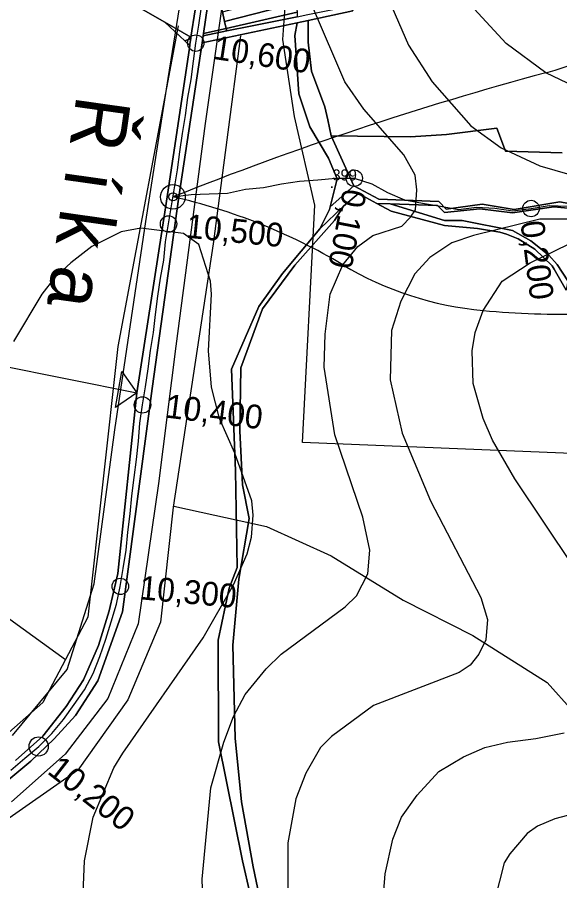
# Model space of a CAD drawing. Extents: x -510989 to -501240, y -1184665 to -1176089.
# Drawn here: x -509339.7 to -509042.8, y -1180518.8 to -1180046.7 of the extents above; entities that cross this region are included whole.
import ezdxf

# ---------------------------------------------------------------- set-up
doc = ezdxf.new("R2010")
doc.units = 0
for name, color, linetype in [('NAVRH_revitalizace_toku', 7, 'Continuous'), ('NAVRH_rozvodnice', 7, 'Continuous'), ('orna_puda', 7, 'Continuous'), ('ostatni_plocha_x_manipulacni_plocha', 7, 'Continuous'), ('ostatni_plocha_x_neplodna_puda', 7, 'Continuous'), ('ostatni_plocha_x_ostatni_komunikace', 7, 'Continuous'), ('STAV_odtokove_linie', 7, 'Continuous'), ('STAV_systematicke_odvodneni', 7, 'Continuous'), ('STAV_vyrazne_udolnice', 7, 'Continuous'), ('trasovani_toku', 7, 'Continuous'), ('trvaly_travni_porost', 7, 'Continuous'), ('vodni_plocha_x_vodni_tok_v_koryt_prir_n_upr', 7, 'Continuous'), ('vodni_plocha_x_vodni_tok_v_koryte_umelem', 7, 'Continuous'), ('vrstevnice_01', 7, 'Continuous'), ('vrstevnice_02', 7, 'Continuous'), ('vrstevnice_05', 7, 'Continuous')]:
    doc.layers.add(name, color=color, linetype=linetype)

msp = doc.modelspace()

# ---------------------------------------------------------------- linework, layer by layer
at = {"layer": 'NAVRH_revitalizace_toku'}
for points in [[(-509251.68, -1180051.44), (-509284.55, -1180226.79), (-509300.99, -1180374.75), (-509325.65, -1180421.33), (-509370.86, -1180461.06), (-509421.55, -1180503.53), (-509437.68, -1180558.22), (-509431.14, -1180593.95), (-509419.28, -1180621.11), (-509382.45, -1180650.58), (-509372.86, -1180654.24)], [(-509217.43, -1180056.92), (-509232.5, -1180170.63), (-509254.42, -1180314.47), (-509261.27, -1180377.49), (-509279.08, -1180419.96), (-509306.48, -1180458.32), (-509365.38, -1180499.42), (-509395.55, -1180530.26), (-509400.81, -1180563.08), (-509388.25, -1180600.36), (-509365.16, -1180623.45), (-509328.69, -1180628.72), (-509284.94, -1180642.09), (-509256.17, -1180678.15), (-509235.24, -1180752.86), (-509207.84, -1180777.52)], [(-509313.32, -1180398.04), (-509397.52, -1180337.11), (-509397.42, -1180166.22)]]:
    msp.add_lwpolyline(points, dxfattribs=at)
at = {"layer": 'NAVRH_rozvodnice'}
for centre, radius, start, end in [((-509104.6, -1179876.43), 207.77, 285.1214, 308.067), ((-508560.17, -1181891.2), 1879.27, 105.12138, 111.68201), ((-509324.71, -1180455.48), 318.43, 59.1866, 77.2585), ((-509068.15, -1180025.32), 182.43, 239.1866, 264.7976), ((-509038.53, -1179700.05), 509.05, 264.7976, 271.1184)]:
    msp.add_arc(centre, radius, start, end, dxfattribs=at)
at = {"layer": 'orna_puda'}
msp.add_lwpolyline([(-509295.45, -1180028.39), (-509258.93, -1180049.38), (-509247.95, -1180059.6), (-509245.26, -1180062.1), (-509245.48, -1180063.57), (-509258.47, -1180150.93), (-509274.3, -1180251.98), (-509284.64, -1180350.9), (-509289.45, -1180371.27), (-509295.29, -1180390.24), (-509303.35, -1180408.89), (-509312.96, -1180423.58), (-509325.64, -1180439.73), (-509340.55, -1180453.11)], dxfattribs=at)
at = {"layer": 'ostatni_plocha_x_manipulacni_plocha'}
for points in [[(-509242.47, -1180018.79), (-509241.92, -1180023.82), (-509242.38, -1180042.72), (-509244.6, -1180057.62), (-509258.93, -1180049.38), (-509295.45, -1180028.39), (-509285.9, -1180026.66), (-509284.8, -1180026.46)], [(-509187, -1180039.03), (-509226.2, -1180048.93), (-509227.45, -1180043.8), (-509187.67, -1180033.24)], [(-509235.55, -1180040.66), (-509235.25, -1180037.15), (-509230.29, -1180040.79), (-509227.72, -1180042.68), (-509227.45, -1180043.8), (-509226.2, -1180048.93), (-509225.27, -1180052.78), (-509237.8, -1180055.64)], [(-509186.43, -1180043.93), (-509225.27, -1180052.78), (-509226.2, -1180048.93), (-509187, -1180039.03)], [(-509186.43, -1180043.93), (-509186.43, -1180046.39), (-509212.09, -1180051.51), (-509224.93, -1180054.2), (-509225.27, -1180052.78)], [(-509258.93, -1180049.38), (-509244.6, -1180057.62), (-509244.71, -1180058.34), (-509247.95, -1180059.6)], [(-509225.27, -1180052.78), (-509224.93, -1180054.2), (-509237.99, -1180056.93), (-509237.8, -1180055.64)], [(-509244.71, -1180058.34), (-509245.15, -1180061.38), (-509245.26, -1180062.1), (-509247.95, -1180059.6)]]:
    msp.add_lwpolyline(points, close=True, dxfattribs=at)
at = {"layer": 'ostatni_plocha_x_neplodna_puda'}
msp.add_lwpolyline([(-509038.45, -1180190.81), (-509044.32, -1180181.95), (-509048.75, -1180176.83), (-509058.64, -1180169), (-509068.7, -1180163.19), (-509096.17, -1180157.8), (-509105.89, -1180157.8), (-509135.59, -1180148.69), (-509109.66, -1180149.58), (-509105.95, -1180153.4), (-509086.5, -1180151.39), (-509068.63, -1180153.64), (-509046.12, -1180150.29), (-509034.36, -1180151.41)], dxfattribs=at)
at = {"layer": 'ostatni_plocha_x_ostatni_komunikace'}
for points in [[(-509186.43, -1180049.67), (-509180.52, -1180048.42), (-509180.52, -1180060.29), (-509178.61, -1180076.11), (-509171.35, -1180095.75), (-509169.79, -1180102.81), (-509167.85, -1180111.56), (-509155.46, -1180138.91), (-509168.42, -1180150.25), (-509164.71, -1180134.95), (-509169.36, -1180123.76), (-509179.59, -1180106.58), (-509185.51, -1180088.6), (-509187.73, -1180056.66)], [(-509135.59, -1180148.69), (-509105.89, -1180157.8), (-509096.17, -1180157.8), (-509068.7, -1180163.19), (-509058.64, -1180169), (-509048.75, -1180176.83), (-509044.32, -1180181.95), (-509038.45, -1180190.81), (-509039.27, -1180195.94), (-509045.97, -1180184.34), (-509047.01, -1180182.52), (-509056.51, -1180173.57), (-509065.59, -1180167.75), (-509071.96, -1180165.22), (-509075.7, -1180164.19), (-509087.89, -1180162.13), (-509105.87, -1180160.5), (-509135.12, -1180152.73), (-509143, -1180148.43)]]:
    msp.add_lwpolyline(points, close=True, dxfattribs=at)
msp.add_lwpolyline([(-509203.81, -1180562.6), (-509216.38, -1180507.98), (-509229.61, -1180442.89), (-509229.67, -1180387.28), (-509223.78, -1180358.88), (-509219.42, -1180347.51), (-509220.24, -1180294.77), (-509222.37, -1180239.03), (-509207.46, -1180204.82), (-509194.45, -1180186.78), (-509174.08, -1180162.44), (-509161.12, -1180149.98), (-509166.12, -1180157.81), (-509187.86, -1180182.31), (-509205.4, -1180206.19), (-509217.39, -1180238.45), (-509217.84, -1180272.78), (-509216.36, -1180302.36), (-509212.75, -1180320.81), (-509218.35, -1180353.83), (-509221.78, -1180389.98), (-509220.38, -1180440.93), (-509216.98, -1180475.74), (-509210.56, -1180511.17), (-509202.62, -1180549.54)], dxfattribs=at)
at = {"layer": 'STAV_odtokove_linie'}
msp.add_line((-509601.08, -1180186.4), (-509274.3, -1180251.98), dxfattribs=at)
msp.add_lwpolyline([(-509282.4, -1180240.38), (-509274.3, -1180251.98), (-509285.9, -1180260.08)], close=True, dxfattribs=at)
at = {"layer": 'STAV_systematicke_odvodneni'}
for p, q in [((-509225.69, -1180026.46), (-509236.86, -1180104.7)), ((-509257.1, -1180080.2), (-509249.66, -1180033.9)), ((-509194.3, -1180058.93), (-509192.71, -1180034.44)), ((-509187.92, -1180100.97), (-509194.3, -1180058.93)), ((-509269.34, -1180158.43), (-509257.1, -1180080.2)), ((-509176.75, -1180149.4), (-509187.92, -1180100.97)), ((-509236.86, -1180104.7), (-509252.82, -1180226.57)), ((-509183.66, -1180279.26), (-509176.75, -1180149.4)), ((-509286.36, -1180272.33), (-509269.34, -1180158.43)), ((-509252.82, -1180226.57), (-509262.4, -1180301.61)), ((-509297.54, -1180356.41), (-509286.36, -1180272.33)), ((-508870.33, -1180292.03), (-509183.66, -1180279.26)), ((-509262.4, -1180301.61), (-509273.57, -1180378.25)), ((-509312.43, -1180403.25), (-509297.54, -1180356.41)), ((-509273.57, -1180378.25), (-509290.06, -1180419.23)), ((-509342.22, -1180439.44), (-509312.43, -1180403.25)), ((-509290.06, -1180419.23), (-509313.47, -1180449.56)), ((-509313.47, -1180449.56), (-509342.73, -1180475.64))]:
    msp.add_line(p, q, dxfattribs=at)
at = {"layer": 'STAV_vyrazne_udolnice'}
msp.add_lwpolyline([(-509253.95, -1180313.92), (-509203.31, -1180325.17), (-509167.94, -1180341.24), (-509128.55, -1180365.35), (-509090.37, -1180384.63), (-509049.78, -1180410.34), (-509035.71, -1180426.01), (-509017.22, -1180447.3), (-508987.08, -1180468.59)], dxfattribs=at)
at = {"layer": 'trasovani_toku'}
for p, q in [((-509240.27, -1180050.98), (-509238.87, -1180041.08)), ((-509242, -1180060.83), (-509240.27, -1180050.98)), ((-509243.31, -1180070.75), (-509242, -1180060.83)), ((-509244.55, -1180080.67), (-509243.31, -1180070.75)), ((-509246.36, -1180090.5), (-509244.55, -1180080.67)), ((-509247.61, -1180100.43), (-509246.36, -1180090.5)), ((-509249.21, -1180110.3), (-509247.61, -1180100.43)), ((-509250.75, -1180120.18), (-509249.21, -1180110.3)), ((-509251.99, -1180130.1), (-509250.75, -1180120.18)), ((-509253.69, -1180139.95), (-509251.99, -1180130.1)), ((-509195.09, -1180137.73), (-509185.18, -1180136.35)), ((-509185.18, -1180136.35), (-509175.21, -1180135.59)), ((-509175.21, -1180135.59), (-509165.26, -1180134.65)), ((-509165.26, -1180134.65), (-509155.26, -1180134.69)), ((-509155.26, -1180134.69), (-509145.74, -1180137.75)), ((-509255.26, -1180149.83), (-509253.69, -1180139.95)), ((-509224.58, -1180142.89), (-509214.85, -1180140.61)), ((-509214.85, -1180140.61), (-509204.88, -1180139.74)), ((-509204.88, -1180139.74), (-509195.09, -1180137.73)), ((-509145.74, -1180137.75), (-509136.99, -1180142.59)), ((-509254.48, -1180144.89), (-509244.57, -1180143.51)), ((-509244.57, -1180143.51), (-509234.57, -1180143.31)), ((-509234.57, -1180143.31), (-509224.58, -1180142.89)), ((-509136.99, -1180142.59), (-509127.77, -1180146.47)), ((-509127.77, -1180146.47), (-509117.95, -1180148.38)), ((-509256.87, -1180159.7), (-509255.26, -1180149.83)), ((-509117.95, -1180148.38), (-509108.08, -1180149.98)), ((-509108.08, -1180149.98), (-509098.26, -1180151.84)), ((-509098.26, -1180151.84), (-509088.34, -1180150.53)), ((-509088.34, -1180150.53), (-509078.36, -1180151.11)), ((-509078.36, -1180151.11), (-509068.47, -1180152.58)), ((-509068.47, -1180152.58), (-509058.55, -1180151.27)), ((-509058.55, -1180151.27), (-509048.69, -1180149.61)), ((-509048.69, -1180149.61), (-509038.7, -1180149.98)), ((-509258.52, -1180169.56), (-509256.87, -1180159.7)), ((-509259.51, -1180179.51), (-509258.52, -1180169.56)), ((-509261.2, -1180189.37), (-509259.51, -1180179.51)), ((-509262.66, -1180199.26), (-509261.2, -1180189.37)), ((-509263.99, -1180209.17), (-509262.66, -1180199.26)), ((-509265.19, -1180219.1), (-509263.99, -1180209.17)), ((-509266.84, -1180228.96), (-509265.19, -1180219.1)), ((-509268.06, -1180238.89), (-509266.84, -1180228.96)), ((-509269.54, -1180248.78), (-509268.06, -1180238.89)), ((-509271.12, -1180258.65), (-509269.54, -1180248.78)), ((-509272.64, -1180268.54), (-509271.12, -1180258.65)), ((-509273.32, -1180278.51), (-509272.64, -1180268.54)), ((-509274.46, -1180288.45), (-509273.32, -1180278.51)), ((-509275.71, -1180298.37), (-509274.46, -1180288.45)), ((-509276.89, -1180308.3), (-509275.71, -1180298.37)), ((-509277.9, -1180318.25), (-509276.89, -1180308.3)), ((-509279.16, -1180328.17), (-509277.9, -1180318.25)), ((-509280.06, -1180338.13), (-509279.16, -1180328.17)), ((-509281.64, -1180348), (-509280.06, -1180338.13)), ((-509283.29, -1180357.87), (-509281.64, -1180348)), ((-509285.33, -1180367.66), (-509283.29, -1180357.87)), ((-509288.23, -1180377.23), (-509285.33, -1180367.66)), ((-509291.17, -1180386.78), (-509288.23, -1180377.23)), ((-509294.43, -1180396.24), (-509291.17, -1180386.78)), ((-509298.13, -1180405.53), (-509294.43, -1180396.24)), ((-509302.8, -1180414.37), (-509298.13, -1180405.53)), ((-509308.59, -1180422.52), (-509302.8, -1180414.37)), ((-509314.4, -1180430.66), (-509308.59, -1180422.52)), ((-509320.79, -1180438.35), (-509314.4, -1180430.66)), ((-509327.94, -1180445.35), (-509320.79, -1180438.35)), ((-509335.55, -1180451.84), (-509327.94, -1180445.35)), ((-509343.1, -1180458.39), (-509335.55, -1180451.84))]:
    msp.add_line(p, q, dxfattribs=at)
for centre, radius in [((-509242, -1180060.83), 4.5), ((-509155.26, -1180134.69), 4.5), ((-509254.48, -1180144.89), 6.75), ((-509254.48, -1180144.89), 2.25), ((-509058.55, -1180151.27), 4.5), ((-509256.87, -1180159.7), 4.5), ((-509271.12, -1180258.65), 4.5), ((-509283.29, -1180357.87), 4.5), ((-509327.94, -1180445.35), 5.25)]:
    msp.add_circle(centre, radius, dxfattribs=at)
at = {"layer": 'trvaly_travni_porost'}
msp.add_lwpolyline([(-509156.1, -1180043.26), (-509180.52, -1180048.42), (-509186.43, -1180049.67), (-509238.55, -1180060.68), (-509237.99, -1180056.93), (-509224.93, -1180054.2), (-509212.09, -1180051.51), (-509186.43, -1180046.39), (-509180.67, -1180045.24), (-509156.89, -1180040.5)], close=True, dxfattribs=at)
for points in [[(-509041.46, -1180120.8), (-509072.54, -1180119.92), (-509077.32, -1180107.35), (-509104.78, -1180110.81), (-509124.57, -1180112.08), (-509167.85, -1180111.56), (-509169.79, -1180102.81), (-509171.35, -1180095.75), (-509178.61, -1180076.11), (-509180.52, -1180060.29), (-509180.52, -1180048.42), (-509156.1, -1180043.26)], [(-509400.71, -1180510.32), (-509332.19, -1180453.34), (-509319.43, -1180441.23), (-509307.74, -1180428.39), (-509295.64, -1180409.44), (-509281.99, -1180371.77), (-509265.78, -1180249.69), (-509251.17, -1180144.87), (-509238.55, -1180060.68), (-509186.43, -1180049.67), (-509187.73, -1180056.66), (-509185.51, -1180088.6), (-509179.59, -1180106.58), (-509169.36, -1180123.76), (-509164.71, -1180134.95), (-509168.42, -1180150.25), (-509168.81, -1180151.87), (-509174.08, -1180162.44), (-509194.45, -1180186.78), (-509207.46, -1180204.82), (-509222.37, -1180239.03), (-509220.24, -1180294.77), (-509219.42, -1180347.51), (-509223.78, -1180358.88), (-509229.67, -1180387.28), (-509229.61, -1180442.89), (-509216.38, -1180507.98), (-509203.81, -1180562.6)], [(-509034.22, -1180149.29), (-509042.85, -1180147.67), (-509067.81, -1180151.76), (-509085.27, -1180148.92), (-509105.06, -1180151.58), (-509109.02, -1180147.44), (-509141.87, -1180146.21), (-509155.46, -1180138.91), (-509167.85, -1180111.56), (-509124.57, -1180112.08), (-509104.78, -1180110.81), (-509077.32, -1180107.35), (-509072.54, -1180119.92), (-509041.46, -1180120.8)], [(-509202.62, -1180549.54), (-509210.56, -1180511.17), (-509216.98, -1180475.74), (-509220.38, -1180440.93), (-509221.78, -1180389.98), (-509218.35, -1180353.83), (-509212.75, -1180320.81), (-509216.36, -1180302.36), (-509217.84, -1180272.78), (-509217.39, -1180238.45), (-509205.4, -1180206.19), (-509187.86, -1180182.31), (-509166.12, -1180157.81), (-509161.12, -1180149.98), (-509152.89, -1180143.02), (-509143, -1180148.43), (-509135.12, -1180152.73), (-509105.87, -1180160.5), (-509087.89, -1180162.13), (-509075.7, -1180164.19), (-509071.96, -1180165.22), (-509065.59, -1180167.75), (-509056.51, -1180173.57), (-509047.01, -1180182.52), (-509045.97, -1180184.34), (-509039.27, -1180195.94)]]:
    msp.add_lwpolyline(points, dxfattribs=at)
at = {"layer": 'vodni_plocha_x_vodni_tok_v_koryt_prir_n_upr'}
msp.add_lwpolyline([(-509034.36, -1180151.41), (-509046.12, -1180150.29), (-509068.63, -1180153.64), (-509086.5, -1180151.39), (-509105.95, -1180153.4), (-509109.66, -1180149.58), (-509135.59, -1180148.69), (-509143, -1180148.43), (-509152.89, -1180143.02), (-509161.12, -1180149.98), (-509174.08, -1180162.44), (-509168.81, -1180151.87), (-509168.42, -1180150.25), (-509155.46, -1180138.91), (-509141.87, -1180146.21), (-509109.02, -1180147.44), (-509105.06, -1180151.58), (-509085.27, -1180148.92), (-509067.81, -1180151.76), (-509042.85, -1180147.67), (-509034.22, -1180149.29)], dxfattribs=at)
at = {"layer": 'vodni_plocha_x_vodni_tok_v_koryte_umelem'}
for points in [[(-509235.55, -1180040.66), (-509237.8, -1180055.64), (-509237.99, -1180056.93), (-509238.55, -1180060.68), (-509251.17, -1180144.87), (-509265.78, -1180249.69), (-509281.99, -1180371.77), (-509295.64, -1180409.44), (-509307.74, -1180428.39), (-509319.43, -1180441.23), (-509332.19, -1180453.34), (-509400.71, -1180510.32)], [(-509340.55, -1180453.11), (-509325.64, -1180439.73), (-509312.96, -1180423.58), (-509303.35, -1180408.89), (-509295.29, -1180390.24), (-509289.45, -1180371.27), (-509284.64, -1180350.9), (-509274.3, -1180251.98), (-509258.47, -1180150.93), (-509245.48, -1180063.57), (-509245.26, -1180062.1), (-509245.15, -1180061.38), (-509244.71, -1180058.34), (-509244.6, -1180057.62), (-509242.38, -1180042.72)]]:
    msp.add_lwpolyline(points, dxfattribs=at)
at = {"layer": 'vrstevnice_01'}
for points in [[(-509237.91, -1180534), (-509238.5, -1180518), (-509233.81, -1180468), (-509226.69, -1180443), (-509221.31, -1180429), (-509215, -1180417), (-509203.41, -1180403), (-509195.31, -1180395), (-509160.19, -1180369), (-509154, -1180363), (-509147.81, -1180351), (-509146.69, -1180338), (-509150.59, -1180320), (-509165.91, -1180275), (-509171.81, -1180238), (-509171.19, -1180220), (-509168.5, -1180198), (-509161.59, -1180182), (-509153.31, -1180172), (-509145.19, -1180166), (-509129.19, -1180161), (-509124.5, -1180156), (-509121.81, -1180152), (-509121, -1180141), (-509121.91, -1180133), (-509128.09, -1180122), (-509150.09, -1180097), (-509160.41, -1180082), (-509177.5, -1180042)], [(-509019.09, -1180092), (-509050.41, -1180077), (-509072.09, -1180061), (-509089.69, -1180042)], [(-509035.31, -1180347), (-509067.41, -1180299), (-509079.59, -1180278), (-509084.69, -1180266), (-509090.19, -1180247), (-509090.69, -1180229), (-509089.09, -1180219), (-509084.69, -1180207), (-509074.41, -1180191), (-509059, -1180181), (-509024.19, -1180164)], [(-509140, -1180536), (-509138.31, -1180515), (-509134.19, -1180496), (-509129.41, -1180484), (-509120.91, -1180472), (-509109, -1180459), (-509095.5, -1180451), (-509083.91, -1180446), (-509071.5, -1180443), (-509055.91, -1180441), (-509040.5, -1180438)]]:
    msp.add_lwpolyline(points, dxfattribs=at)
at = {"layer": 'vrstevnice_02'}
for points in [[(-509140.69, -1180027), (-509125.5, -1180062), (-509112.59, -1180082), (-509091.41, -1180106), (-509074.81, -1180118), (-509053.81, -1180128), (-509029.19, -1180135)], [(-509031.41, -1180157), (-509053.81, -1180157), (-509090, -1180166), (-509101.81, -1180170), (-509113.91, -1180178), (-509122.09, -1180187), (-509129.81, -1180202), (-509134.81, -1180218), (-509135.59, -1180245), (-509129.09, -1180274), (-509113.5, -1180311), (-509086.09, -1180364), (-509082.31, -1180376), (-509083.19, -1180387), (-509087.19, -1180395), (-509091.91, -1180401), (-509097.91, -1180405), (-509144.69, -1180423), (-509167.69, -1180440), (-509173.81, -1180446), (-509181.81, -1180460), (-509187.19, -1180474), (-509191.69, -1180498), (-509191.69, -1180531)], [(-509303.81, -1180530), (-509302.91, -1180508), (-509298.19, -1180484), (-509286.91, -1180457), (-509281.81, -1180449), (-509237.91, -1180386), (-509221.31, -1180357), (-509213.81, -1180340), (-509211.5, -1180331), (-509210.59, -1180319), (-509211.31, -1180311), (-509220.69, -1180285), (-509229.09, -1180266), (-509233.31, -1180249), (-509235, -1180229), (-509233.31, -1180198), (-509233.91, -1180191), (-509240.31, -1180171), (-509248.69, -1180165), (-509272.09, -1180162), (-509282.81, -1180164), (-509298.81, -1180172), (-509310.41, -1180181), (-509319.19, -1180189), (-509326.19, -1180198), (-509341.69, -1180224)], [(-509019.31, -1180478), (-509045.5, -1180485), (-509055, -1180489), (-509060.69, -1180493), (-509070.19, -1180504), (-509073.19, -1180509), (-509078.31, -1180529), (-509079.19, -1180552), (-509077.5, -1180572), (-509072.31, -1180593), (-509037.19, -1180687)]]:
    msp.add_lwpolyline(points, dxfattribs=at)

# ---------------------------------------------------------------- texts
at = {"layer": 'trasovani_toku'}
for s, height, rotation, p in [('10,600', 13, 351.3201, (-509232.95, -1180069.41)), ('Ř í k a', 30, 261.961, (-509307.11, -1180088.67)), ('0,100', 13, 258.8397, (-509161.19, -1180139.78)), ('10,500', 13, 354.287, (-509247.65, -1180167.15)), ('0,200', 13, 277.3965, (-509064.4, -1180158.72)), ('10,400', 13, 352.9591, (-509259.01, -1180265.49)), ('10,300', 13, 354.8034, (-509273.22, -1180364.86)), ('10,200', 13, 322.1133, (-509323.84, -1180459.78))]:
    msp.add_text(s, height=height, rotation=rotation, dxfattribs=at).set_placement(p)
at = {"layer": 'vrstevnice_05'}
for s, p in [('399', (-509167.22, -1180135.9)), ('.', (-509168.64, -1180140.01))]:
    msp.add_text(s, height=6, dxfattribs=at).set_placement(p)

doc.saveas('drawing.dxf')
